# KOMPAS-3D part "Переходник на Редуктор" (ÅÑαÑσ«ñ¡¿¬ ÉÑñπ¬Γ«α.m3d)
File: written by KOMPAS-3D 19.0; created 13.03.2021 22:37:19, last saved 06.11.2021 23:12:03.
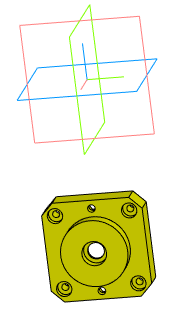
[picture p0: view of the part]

Document properties: Автор: Agent Smith; Полное имя файла: D:\3D_print\3D проекты Компас 3D\Редуктор (Снова)\Переходник Редуктор.m3d

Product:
- Part/product: Переходник на Редуктор
    Материал: АБС 0603Т ТУ 2214-019-002 03521-96 (density 0 kg/m3)
  - Body: Тело 1
      Масса: 0.106851

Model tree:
1. Эскиз:1  (with: Элемент выдавливания:9)  (labels: Переходник на Nema_17)
2. Элемент выдавливания:1
     Расстояние 1 = 6
3. Эскиз:2  (with: Элемент выдавливания:1)
4. Элемент выдавливания:2
     Расстояние 2 = 3
5. Эскиз:3  (with: Элемент выдавливания:1)
6. Элемент выдавливания:3
     Расстояние 2 = 3
7. Элемент выдавливания:4  (with: Элемент выдавливания:1)
     Расстояние 1 = 2
8. Элемент выдавливания:5  (with: Элемент выдавливания:4, Элемент выдавливания:11)  (labels: Переходник на Nema_17)
     Расстояние 1 = 2
9. Эскиз:4  (with: Элемент выдавливания:1)
10. Элемент выдавливания:6  (with: Элемент выдавливания:9)  (labels: Переходник на Nema_17)
     Расстояние 1 = 6
11. Эскиз:5  (with: Элемент выдавливания:6)
12. Элемент выдавливания:7
     Расстояние 2 = 5.8
13. Эскиз:6  (with: Элемент выдавливания:6)
14. Элемент выдавливания:8
     Расстояние 2 = 4.4
15. Эскиз:7  (with: Элемент выдавливания:8)
16. Элемент выдавливания:9  (labels: АБС 0603Т ТУ 2214-019-002 03521-96)
     Расстояние 2 = 11.6

Referenced files in D:\3D_print\3D проекты Компас 3D\Халява Projects 5\: Намоточный станок (Projects 6).a3d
